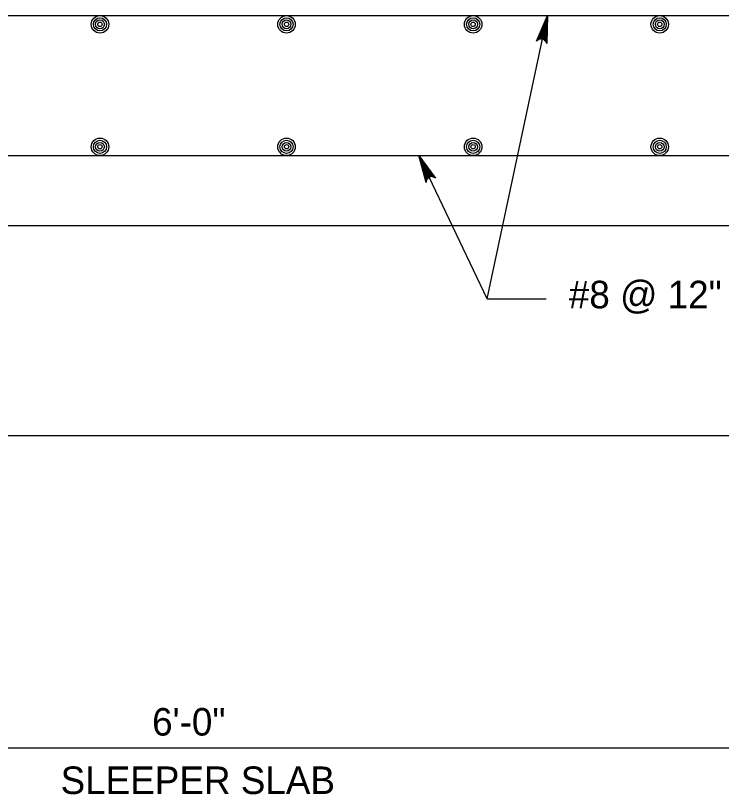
# Model space of a CAD drawing. Extents: x 638079 to 640019, y 297691 to 298879.
# Drawn here: x 639327.7 to 639404.5, y 298444 to 298528.9 of the extents above; entities that cross this region are included whole.
import ezdxf

# ---------------------------------------------------------------- set-up
doc = ezdxf.new("R2010")
doc.units = 0
doc.layers.add('1', color=7, linetype='Continuous')

msp = doc.modelspace()

# ---------------------------------------------------------------- linework, layer by layer
at = {"layer": '1'}
for p, q in [((639273.36, 298528.862), (639441, 298528.862)), ((639379.046, 298498.029), (639385.582, 298528.862)), ((639273.36, 298513.622), (639441, 298513.622)), ((639379.046, 298498.029), (639371.593, 298513.622)), ((639265.74, 298506.002), (639448.62, 298506.002)), ((639379.046, 298498.029), (639385.469, 298498.029)), ((639250.5, 298483.142), (639463.86, 298483.142)), ((639223.406, 298449.105), (639448.62, 298449.105))]:
    msp.add_line(p, q, dxfattribs=at)
for points in [[(639385.582, 298528.862), (639385.511, 298525.829), (639385.456, 298525.957), (639385.402, 298526.086), (639385.317, 298526.165), (639385.231, 298526.244), (639385.137, 298526.281), (639385.043, 298526.319), (639384.941, 298526.323), (639384.84, 298526.327), (639384.73, 298526.29), (639384.62, 298526.252), (639384.518, 298526.156), (639384.416, 298526.06), (639385.582, 298528.862), (639384.518, 298526.156), (639384.62, 298526.252), (639385.582, 298528.862), (639384.73, 298526.29), (639384.84, 298526.327), (639385.582, 298528.862), (639384.941, 298526.323), (639385.043, 298526.319), (639385.582, 298528.862), (639385.137, 298526.281), (639385.231, 298526.244), (639385.582, 298528.862), (639385.317, 298526.165), (639385.402, 298526.086), (639385.582, 298528.862), (639385.456, 298525.957)], [(639371.593, 298513.622), (639373.384, 298511.172), (639373.262, 298511.242), (639373.141, 298511.311), (639373.025, 298511.321), (639372.91, 298511.332), (639372.812, 298511.304), (639372.714, 298511.276), (639372.631, 298511.218), (639372.549, 298511.159), (639372.484, 298511.063), (639372.419, 298510.966), (639372.397, 298510.828), (639372.375, 298510.69), (639371.593, 298513.622), (639372.397, 298510.828), (639372.419, 298510.966), (639371.593, 298513.622), (639372.484, 298511.063), (639372.549, 298511.159), (639371.593, 298513.622), (639372.631, 298511.218), (639372.714, 298511.276), (639371.593, 298513.622), (639372.812, 298511.304), (639372.91, 298511.332), (639371.593, 298513.622), (639373.025, 298511.321), (639373.141, 298511.311), (639371.593, 298513.622), (639373.262, 298511.242)]]:
    msp.add_lwpolyline(points, dxfattribs=at)
for centre, radius in [((639336.86, 298527.911), 0.952), ((639336.86, 298527.911), 0.714), ((639357.18, 298527.911), 0.952), ((639357.18, 298527.911), 0.714), ((639377.5, 298527.911), 0.952), ((639377.5, 298527.911), 0.714), ((639397.821, 298527.911), 0.952), ((639397.821, 298527.911), 0.714), ((639336.86, 298527.911), 0.476), ((639336.86, 298527.911), 0.238), ((639357.18, 298527.911), 0.476), ((639357.18, 298527.911), 0.238), ((639377.5, 298527.911), 0.476), ((639377.5, 298527.911), 0.238), ((639397.821, 298527.911), 0.476), ((639397.821, 298527.911), 0.238), ((639336.86, 298514.573), 0.952), ((639336.86, 298514.573), 0.714), ((639336.86, 298514.573), 0.476), ((639357.18, 298514.573), 0.952), ((639357.18, 298514.573), 0.714), ((639357.18, 298514.573), 0.476), ((639377.5, 298514.573), 0.952), ((639377.5, 298514.573), 0.714), ((639377.5, 298514.573), 0.476), ((639397.821, 298514.573), 0.952), ((639397.821, 298514.573), 0.714), ((639397.821, 298514.573), 0.476), ((639336.86, 298514.573), 0.238), ((639357.18, 298514.573), 0.238), ((639377.5, 298514.573), 0.238), ((639397.821, 298514.573), 0.238)]:
    msp.add_circle(centre, radius, dxfattribs=at)

# ---------------------------------------------------------------- texts
for s, p in [('#8 @ 12"', (639387.923, 298496.979)), ('6\'-0"', (639342.538, 298450.444)), ('SLEEPER SLAB', (639332.574, 298444.078))]:
    msp.add_text(s, height=3, dxfattribs=at).set_placement(p)

doc.saveas('drawing.dxf')
